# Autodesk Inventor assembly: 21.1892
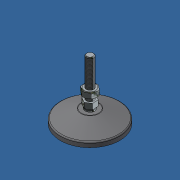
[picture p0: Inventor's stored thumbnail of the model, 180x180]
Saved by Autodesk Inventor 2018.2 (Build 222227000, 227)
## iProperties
Created: 2007-03
Part Number: 21.1892
Document SubType Name: Assembly
Designer: Andy Moles
Description: LEVELING FOOT M10 80mm BASE
Author: Andy Moles
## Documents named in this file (5)
- Y:\INVENTOR LIBRARIES\PARTS LIBRARY\FEET WHEELS FLOOR FASTENING SUPPORTS\21.1892 LEVELING FOOT M10 80mm BASE.iam
- Y:\INVENTOR LIBRARIES\PARTS LIBRARY\FASTENING ELEMENTS\NUTS\21.1527 M10 HEX NUT.ipt
- Y:\INVENTOR LIBRARIES\PARTS LIBRARY\FEET WHEELS FLOOR FASTENING SUPPORTS\SUBCOMPONENTS\LEVELING FEET SUBCOMPONENTS\PAD 80mm PLASTIC.ipt
- Y:\INVENTOR LIBRARIES\PARTS LIBRARY\FEET WHEELS FLOOR FASTENING SUPPORTS\SUBCOMPONENTS\LEVELING FEET SUBCOMPONENTS\ANTI-SKID PAD 80mm.ipt
- Y:\INVENTOR LIBRARIES\PARTS LIBRARY\FEET WHEELS FLOOR FASTENING SUPPORTS\SUBCOMPONENTS\LEVELING FEET SUBCOMPONENTS\THREADED STUD 10mm LONGER.ipt
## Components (4 placed, 4 different names)
1. ANTI-SKID PAD 80mm:1 — Insert:1
2. PAD 80mm PLASTIC:1 — Insert:1, Tangent:1, Mate:1
3. THREADED STUD 10mm LONGER:1 — Tangent:1, Mate:1, Mate:2
4. 21.1527 M10 HEX NUT:1 — Mate:2
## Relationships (4: Mate 2, Insert 1, Tangent 1)
- Insert:1: ANTI-SKID PAD 80mm:1 ↔ PAD 80mm PLASTIC:1
- Tangent:1: PAD 80mm PLASTIC:1 ↔ THREADED STUD 10mm LONGER:1
- Mate:1: PAD 80mm PLASTIC:1 ↔ THREADED STUD 10mm LONGER:1
- Mate:2: THREADED STUD 10mm LONGER:1 ↔ 21.1527 M10 HEX NUT:1
